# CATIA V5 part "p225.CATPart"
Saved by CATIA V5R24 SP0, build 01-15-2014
Part number: blue
Bounding box of the stored display mesh (mm): x -20 to 937.588, y -1742.298 to 2076.426, z -239.629 to 463.435
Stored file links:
  D:\CADLAB\2023lab\final\steam_final\p25.CATPart
  D:\CADLAB\2023lab\final\steam\p25.CATPart
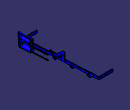
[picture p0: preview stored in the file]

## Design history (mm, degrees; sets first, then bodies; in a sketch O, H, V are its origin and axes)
AxisSystem1: origin (0, 0, 0), X (1, 0, 0), Y (0, 1, 0), Z (0, 0, 1)
Body1 (main body)
  Body2 "Body from original PartBody"
    Solid1: linked copy from another document
  Assemble1: tool Body2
